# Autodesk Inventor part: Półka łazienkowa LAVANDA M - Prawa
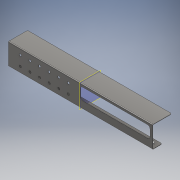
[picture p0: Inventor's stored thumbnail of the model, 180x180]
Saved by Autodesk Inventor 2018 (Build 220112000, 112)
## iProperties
Created: 2020-02
Part Number: Półka łazienkowa LAVANDA M - Prawa
Material: Ogólny
Document SubType Name: Modeling
Designer: Marcel
Density: 1 g/cm^3
Appearance: Domyślna
Author: Marcel
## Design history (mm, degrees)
derived "Półka łazienkowa LAVANDA M - Prawa.iam"
node "Bryła1"
node "Uchwyt na ręcznik 1 - 60 cm prawa.ipt:1"
node "Płaszczyzna konstrukcyjna1"
node "Kapselek.ipt:1"
node "Kapselek.ipt:2"
